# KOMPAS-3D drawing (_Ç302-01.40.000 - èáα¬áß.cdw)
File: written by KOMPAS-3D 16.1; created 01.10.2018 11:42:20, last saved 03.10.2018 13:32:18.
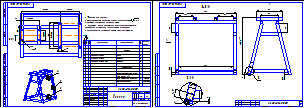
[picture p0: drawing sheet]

Sheets 1-2: A3, landscape

Title block, sheet 1: name: Каркас; designation: А302-01.40.000; mass: 3,82; scale: 1:1; sheet number: 1; sheets: 2; organisation: ЗАО «Астерион»; sheet format: A3; stored path: \\192.168.87.28\Konstructor_doc\Мембранные насосы\Мембранный электропривод\А302-00.00.000 - ASTRA-302 (МЭ200)\3Д ПВХ\А302-01.40.000 - Каркас.cdw; drawn by: Милов; technical control: Лучихин
Title block, sheet 2: sheet number: 2

Views: Вид 1, Спереди, Разрез А-А, Вид по стрелке 3, Местный разрез 1, Вид 4, Вид:1, Выносной элемент 5, Выносной элемент Б, Выносной элемент
Referenced files in \\192.168.87.28\Konstructor_doc\Мембранные насосы\Мембранный электропривод\А302-00.00.000 - ASTRA-302 (МЭ200)\3Д ПВХ\: А302-01.40.000 - Каркас.a3d
Referenced files in \\192.168.87.28\Konstructor_doc\Мембранные насосы\Мембранный электропривод\А302-00.00.000 - ASTRA-302 (МЭ200)\3Д ПВХ\Отработка\: Труба профильная 25х25х1,5.m3d, Труба профильная 25х25х1,5-2.m3d, А302-01.40.002-01 - Стяжка.m3d
Referenced files in Z:\Мембранные насосы\Мембранный электропривод\А302-00.00.000 - ASTRA-302 (МЭ200)\3Д ПВХ\: А302-01.40.001 - Опора.cdw, А302-01.40.002 - Стяжка.cdw, А302-01.40.000 - Каркас.a3d
Referenced files: graphic.tdp
Referenced files in Z:\Мембранные насосы\Мембранный электропривод\А302-00.00.000 - ASTRA-302 (МЭ200)\3Д ПВХ\Отработка\: Труба профильная 25х25х1,5.m3d, Труба профильная 25х25х1,5-1.m3d, А302-01.40.002-01 - Стяжка.m3d, Труба профильная 25х25х1,5-2.m3d
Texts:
  *Размеры для справок.
  Шероховатость дорабатываемых поверхностей  Ra 6,3 .
  Профили сварить по контуру  .
  Покрытие: Эмаль порошковая эпоксидно-полиэфирная,
  цвет RAL5005, шагрень (допускается глянцевая).
  Общие допуски ГОСТ 30893.2-mK (H14, h14,  t2/2).
  Труба профильная 20х20х1,5
  Ст3 ГОСТ 380-2005
  Труба
  профильная
  ГОСТ
  м с учетом
  деталей
  м с учетом деталей
  Опора
  Стяжка
  Заглушка квадратная черная 20х20 мм
  арт. 20-20 СЧС
  Заглушка
  квадратная
  черная
  арт
  СЧС
  Лит-Масса-Масштаб
  Материал-Предприятие
  Title Specification
  Body Specification ( left align )
  Body Specificaton ( centered )
  Поз.
  Кол.
  Приме-
  чание
  Таблица спецификации
  Труба профильная 25х25х1,5
Dimensions and other numbers on the sheet: 10; 120±0,2; 266±0,3; 134±0,2; 70±0,2; 160±0,2; 130; 180; 8 отв.; 20; 420; 380; 100; 60; 10,5; 114; 2; 389,25; 1; 3; 4; 5; 4,5; 1:1; 3,82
